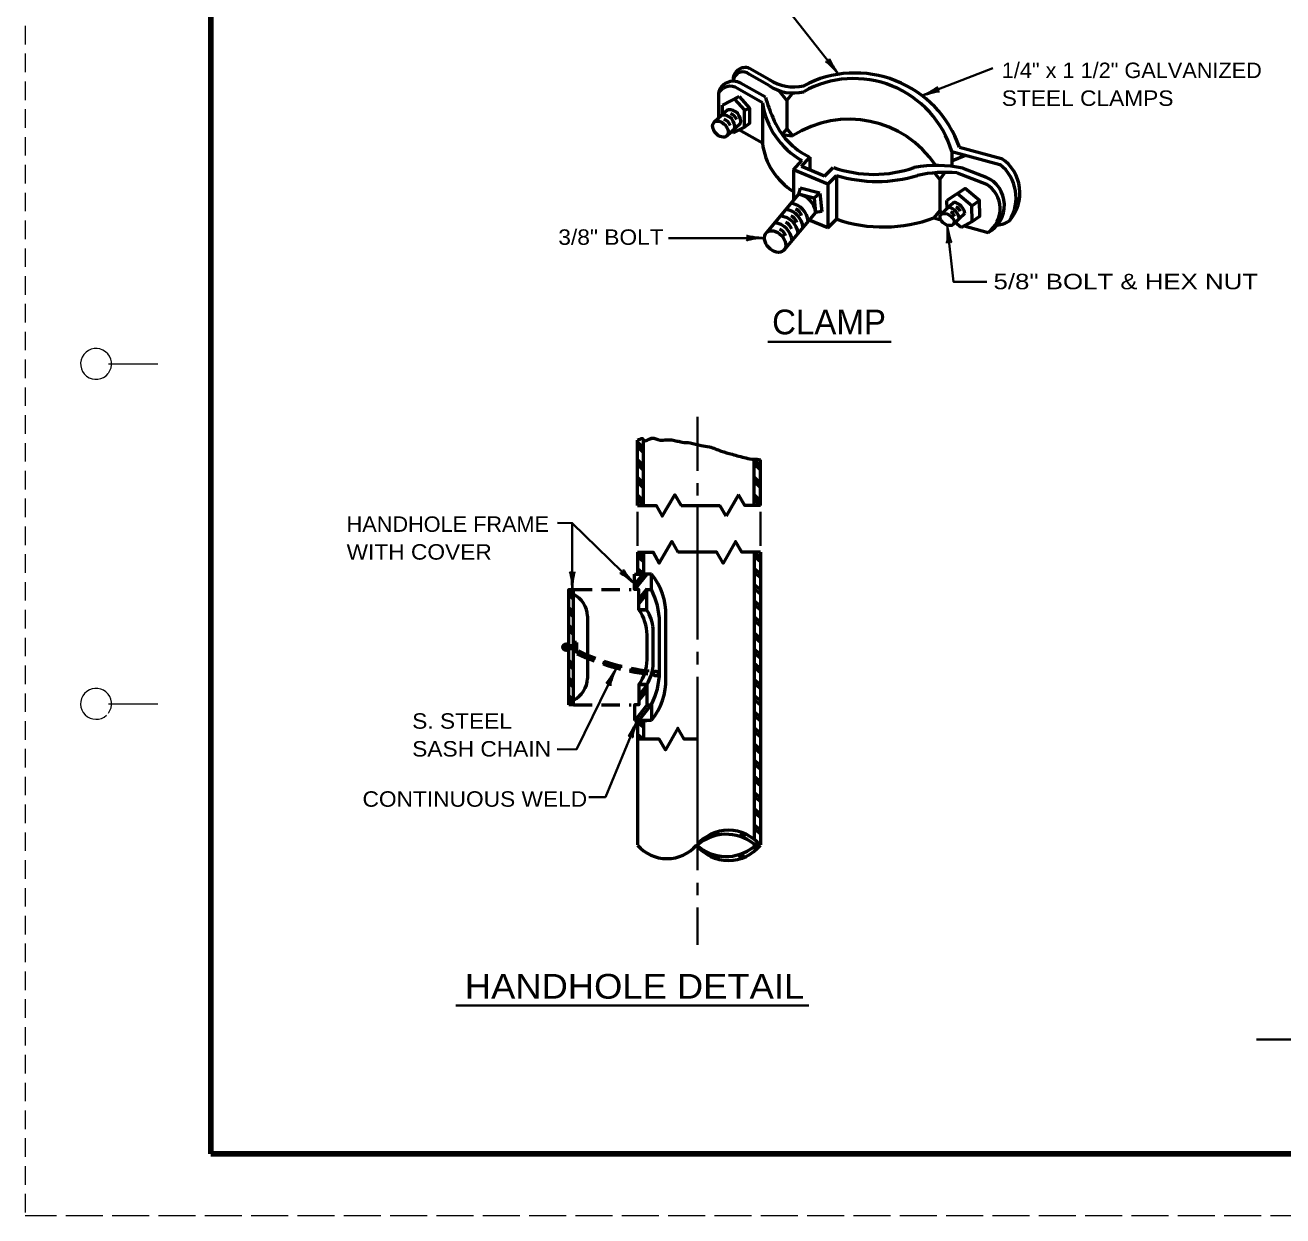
# Model space of a CAD drawing. Extents: x -1 to 679, y -228 to 440.
# Drawn here: x -1 to 202.5, y 0.2 to 192.8 of the extents above; entities that cross this region are included whole.
import ezdxf

# ---------------------------------------------------------------- set-up
doc = ezdxf.new("R2010")
doc.units = 0
doc.linetypes.add('LONG_DASHED', pattern=[7.5, 6, -1.5])
doc.linetypes.add('MEDIUM_DASHED', pattern=[4.5, 3, -1.5])
doc.layers.add('1', color=7, linetype='Continuous', lineweight=35)
doc.layers.add('61', color=7, linetype='Continuous', lineweight=35)

msp = doc.modelspace()

# ---------------------------------------------------------------- hatches: boundary and pattern name
at = {"layer": '1'}
msp.add_hatch(color=256, dxfattribs=at).paths.add_polyline_path([(87.083, 92.208, 1), (85.994, 92.208, 1)])

# ---------------------------------------------------------------- linework, layer by layer
at = {"layer": '1', "linetype": 'MEDIUM_DASHED', "lineweight": 13}
msp.add_line((-0.979, 440.237), (-1.039, 0.197), dxfattribs=at)
at = {"layer": '1', "lineweight": 40}
for p, q in [((120.107, 198.311), (130.625, 184.906)), ((144.15, 181.442), (155.602, 185.881)), ((118.629, 158.401), (103.107, 158.401)), ((119.153, 141.59), (139.165, 141.59)), ((68.685, 34.21), (125.825, 34.21)), ((198.293, 28.717), (261.764, 28.717))]:
    msp.add_line(p, q, dxfattribs=at)
at = {"layer": '1', "lineweight": 53}
for p, q in [((119.441, 184.018), (116.221, 185.858)), ((118.801, 181.178), (114.781, 183.458)), ((119.441, 183.058), (116.221, 184.878)), ((111.181, 181.778), (111.181, 177.758)), ((114.521, 181.298), (111.841, 179.878)), ((118.301, 180.298), (114.281, 182.598)), ((122.241, 180.638), (120.961, 182.278)), ((122.241, 180.638), (123.201, 181.878)), ((112.741, 179.178), (110.481, 177.138)), ((111.841, 178.378), (111.841, 179.878)), ((113.761, 180.898), (115.381, 179.098)), ((118.301, 180.298), (118.301, 173.738)), ((114.761, 176.918), (112.521, 174.898)), ((113.361, 175.678), (113.561, 175.438)), ((118.301, 173.738), (114.501, 175.898)), ((121.761, 175.098), (123.181, 174.918)), ((122.241, 176.098), (123.181, 174.918)), ((150.181, 173.118), (157.001, 171.298)), ((124.641, 169.998), (126.001, 171.498)), ((126.001, 171.498), (126.001, 169.418)), ((148.961, 172.418), (156.741, 170.318)), ((148.961, 172.418), (148.961, 169.998)), ((149.081, 170.958), (151.161, 171.818)), ((123.321, 169.458), (124.681, 170.958)), ((128.901, 167.098), (123.321, 169.458)), ((123.321, 169.458), (123.321, 164.478)), ((128.361, 168.418), (124.641, 169.998)), ((128.361, 168.418), (129.781, 169.838)), ((147.001, 167.898), (147.881, 169.038)), ((150.721, 169.718), (154.501, 168.278)), ((128.901, 167.098), (130.321, 168.518)), ((128.901, 167.098), (128.901, 160.038)), ((130.321, 168.518), (130.321, 161.458)), ((147.001, 167.898), (146.161, 168.958)), ((147.001, 167.898), (147.001, 162.858)), ((149.841, 168.938), (154.561, 167.138)), ((124.161, 165.478), (118.981, 159.298)), ((124.401, 166.458), (124.161, 165.478)), ((126.661, 164.858), (124.161, 165.478)), ((127.581, 165.678), (124.401, 166.458)), ((127.581, 165.678), (126.661, 164.858)), ((127.581, 165.678), (127.921, 162.678)), ((152.181, 163.598), (149.861, 165.538)), ((126.661, 164.858), (126.921, 162.558)), ((149.361, 164.218), (147.141, 162.158)), ((148.181, 163.118), (148.141, 164.478)), ((126.921, 162.558), (121.721, 156.378)), ((128.901, 160.038), (125.881, 161.318)), ((127.921, 162.678), (126.921, 162.558)), ((128.901, 160.038), (130.321, 161.458)), ((147.001, 162.858), (146.061, 161.658)), ((146.061, 161.658), (147.161, 161.358)), ((147.001, 162.858), (147.381, 162.358)), ((151.081, 162.378), (149.241, 160.658)), ((150.481, 160.118), (149.521, 160.918)), ((150.941, 160.358), (154.821, 159.318)), ((98.073, 115.123), (98.073, 125.722)), ((99.073, 124.402), (98.073, 125.402)), ((99.073, 123.682), (98.073, 124.682)), ((99.073, 115.123), (99.073, 125.722)), ((99.073, 121.542), (98.073, 122.542)), ((116.973, 115.123), (116.973, 122.542)), ((117.973, 121.542), (116.973, 122.542)), ((117.973, 115.123), (117.973, 122.542)), ((99.073, 120.822), (98.073, 121.843)), ((117.973, 120.822), (116.973, 121.843)), ((99.073, 118.703), (98.073, 119.703)), ((99.073, 117.983), (98.073, 118.983)), ((117.973, 118.703), (116.973, 119.703)), ((117.973, 117.983), (116.973, 118.983)), ((99.073, 115.843), (98.073, 116.843)), ((99.073, 115.123), (98.073, 116.142)), ((114.453, 116.882), (112.433, 113.382)), ((117.973, 115.843), (116.973, 116.843)), ((117.973, 115.123), (116.973, 116.142)), ((105.133, 115.123), (111.433, 115.123)), ((112.433, 113.382), (111.433, 115.123)), ((98.073, 107.562), (98.073, 104.042)), ((98.073, 107.562), (99.073, 106.742)), ((98.073, 106.922), (99.073, 106.082)), ((99.073, 107.562), (99.073, 104.042)), ((116.973, 107.562), (117.973, 106.742)), ((116.973, 106.922), (117.973, 106.082)), ((117.973, 107.562), (117.973, 60.203)), ((97.573, 104.042), (99.573, 104.042)), ((99.573, 104.042), (97.573, 101.522)), ((98.933, 104.042), (97.573, 102.322)), ((98.073, 104.962), (99.073, 104.123)), ((98.073, 104.302), (98.393, 104.042)), ((100.333, 104.042), (98.313, 104.042)), ((116.973, 104.962), (117.973, 104.123)), ((116.973, 104.302), (117.973, 103.483)), ((116.973, 102.343), (117.973, 101.522)), ((87.733, 100.682), (86.973, 101.442)), ((87.733, 99.983), (86.973, 100.742)), ((87.733, 82.882), (87.733, 101.522)), ((99.573, 101.623), (98.313, 100.042)), ((99.573, 100.822), (98.313, 99.242)), ((116.973, 101.682), (117.973, 100.862)), ((87.733, 97.843), (86.973, 98.602)), ((87.733, 97.123), (86.973, 97.882)), ((99.573, 98.242), (98.313, 98.242)), ((116.973, 99.722), (117.973, 98.903)), ((116.973, 99.082), (117.973, 98.242)), ((87.733, 94.983), (86.973, 95.742)), ((90.013, 97.242), (90.013, 87.162)), ((101.653, 88.162), (101.653, 96.222)), ((102.653, 87.162), (102.653, 97.242)), ((116.973, 97.123), (117.973, 96.282)), ((116.973, 96.462), (117.973, 95.642)), ((87.733, 94.282), (86.973, 95.042)), ((99.633, 90.182), (99.633, 94.222)), ((100.633, 89.182), (100.633, 95.222)), ((116.973, 94.502), (117.973, 93.682)), ((116.973, 93.862), (117.973, 93.022)), ((87.733, 92.442), (86.973, 92.442)), ((87.733, 92.322), (86.973, 92.322)), ((87.733, 92.242), (86.973, 92.242)), ((87.733, 92.242), (86.973, 92.242)), ((87.733, 92.123), (86.973, 92.123)), ((87.733, 92.002), (86.973, 92.002)), ((87.733, 91.942), (86.973, 91.942)), ((88.233, 92.962), (87.733, 92.962)), ((87.853, 92.962), (87.853, 91.442)), ((87.933, 92.962), (87.933, 91.442)), ((87.933, 92.962), (87.933, 91.442)), ((88.013, 92.962), (88.013, 91.442)), ((88.013, 92.962), (88.013, 91.442)), ((88.073, 92.962), (88.073, 91.442)), ((88.133, 92.962), (88.133, 91.442)), ((88.153, 92.962), (88.153, 91.442)), ((88.193, 92.962), (88.193, 91.442)), ((88.233, 92.962), (88.233, 91.442)), ((116.973, 91.903), (117.973, 91.062)), ((87.733, 89.282), (86.973, 90.043)), ((88.233, 91.442), (87.733, 91.442)), ((116.973, 91.242), (117.973, 90.403)), ((116.973, 89.602), (117.973, 88.782)), ((87.733, 88.582), (86.973, 89.322)), ((116.973, 88.962), (117.973, 88.123)), ((87.733, 86.442), (86.973, 87.203)), ((87.733, 85.722), (86.973, 86.483)), ((99.573, 86.022), (98.313, 84.442)), ((116.973, 87.002), (117.973, 86.162)), ((116.973, 86.343), (117.973, 85.522)), ((87.733, 83.582), (86.973, 84.343)), ((87.733, 82.882), (86.973, 83.623)), ((99.573, 85.203), (98.313, 83.642)), ((116.973, 84.382), (117.973, 83.562)), ((116.973, 83.722), (117.973, 82.903)), ((87.733, 82.882), (86.973, 82.882)), ((99.653, 82.882), (97.633, 80.362)), ((100.333, 82.922), (98.273, 80.362)), ((116.973, 81.763), (117.973, 80.942)), ((97.573, 80.362), (99.573, 80.362)), ((98.073, 80.362), (98.073, 77.322)), ((98.073, 80.102), (99.073, 79.263)), ((100.333, 80.362), (98.313, 80.362)), ((98.553, 80.362), (99.073, 79.922)), ((99.073, 80.362), (99.073, 77.322)), ((116.973, 81.123), (117.973, 80.282)), ((98.073, 78.142), (99.053, 77.322)), ((98.073, 77.483), (98.253, 77.322)), ((116.973, 79.162), (117.973, 78.322)), ((116.973, 78.502), (117.973, 77.682)), ((116.973, 76.543), (117.973, 75.722)), ((116.973, 75.903), (117.973, 75.062)), ((116.973, 73.942), (117.973, 73.102)), ((116.973, 73.282), (117.973, 72.442)), ((116.973, 71.322), (117.973, 70.483)), ((116.973, 70.662), (117.973, 69.843)), ((116.973, 68.703), (117.973, 67.882)), ((116.973, 68.062), (117.973, 67.222)), ((116.973, 66.102), (117.973, 65.263)), ((116.973, 65.442), (117.973, 64.623)), ((116.973, 63.482), (117.973, 62.663)), ((110.433, 62.142), (110.633, 61.703)), ((110.913, 62.302), (111.133, 61.802)), ((115.013, 62.203), (114.713, 61.562)), ((115.473, 62.023), (115.193, 61.383)), ((116.973, 62.822), (117.973, 62.002)), ((116.673, 59.722), (117.853, 60.042)), ((116.973, 60.322), (117.613, 60.502)), ((110.613, 58.062), (110.833, 58.523)), ((111.093, 57.922), (111.333, 58.442)), ((114.833, 58.002), (114.533, 58.663)), ((115.313, 58.182), (115.013, 58.822))]:
    msp.add_line(p, q, dxfattribs=at)
at = {"layer": '1'}
for p, q in [((107.773, 120.763), (107.773, 129.502)), ((107.773, 118.763), (107.773, 116.742)), ((98.073, 108.582), (98.073, 114.123)), ((107.773, 115.123), (107.773, 111.362)), ((107.773, 114.722), (107.773, 93.462)), ((117.973, 108.582), (117.973, 114.123)), ((87.519, 112.294), (85.131, 112.307)), ((107.773, 91.442), (107.773, 89.422)), ((107.773, 87.403), (107.773, 56.122)), ((107.773, 54.102), (107.773, 52.082)), ((107.773, 50.082), (107.773, 44.042))]:
    msp.add_line(p, q, dxfattribs=at)
at = {"layer": '1', "linetype": 'MEDIUM_DASHED', "lineweight": 53}
for p, q in [((87.733, 101.522), (97.053, 101.522)), ((87.733, 82.882), (97.053, 82.882))]:
    msp.add_line(p, q, dxfattribs=at)
at = {"layer": '1', "lineweight": 53}
for points in [[(114.521, 181.298), (116.201, 179.438), (116.201, 176.918), (115.381, 176.338), (113.561, 175.438)], [(115.381, 176.338), (115.381, 179.098), (116.201, 179.438)], [(122.241, 180.638), (122.241, 176.098), (121.601, 175.298)], [(150.481, 160.118), (152.261, 161.078), (153.501, 161.938), (153.421, 164.458), (151.101, 166.398), (148.141, 164.478)], [(152.261, 161.078), (152.181, 163.598), (153.421, 164.458)], [(98.073, 115.123), (101.093, 115.123), (102.093, 113.382), (104.113, 116.882), (105.133, 115.123)], [(117.973, 115.123), (115.453, 115.123), (114.453, 116.882)], [(98.073, 107.562), (100.593, 107.562), (101.593, 105.822), (103.613, 109.322), (104.613, 107.562)], [(117.973, 107.562), (114.953, 107.562), (113.953, 109.322), (111.933, 105.822), (110.913, 107.562), (104.613, 107.562)], [(116.973, 107.562), (116.973, 87.123), (116.973, 61.102)], [(98.313, 98.242), (98.313, 101.522), (97.573, 101.522), (97.573, 104.042)], [(98.313, 98.242), (99.573, 98.242), (99.573, 101.522), (100.333, 101.522), (100.333, 104.042)], [(86.973, 82.882), (86.973, 101.522), (87.733, 101.522)], [(99.573, 86.142), (98.313, 86.142), (98.313, 82.882), (97.573, 82.882), (97.573, 80.362)], [(98.313, 86.142), (99.573, 86.142), (99.573, 82.882), (100.333, 82.882), (100.333, 80.362)], [(107.653, 77.322), (105.633, 77.322), (104.613, 79.082), (102.613, 75.582), (101.593, 77.322), (98.073, 77.322), (98.073, 60.203)]]:
    msp.add_lwpolyline(points, dxfattribs=at)
at = {"layer": '1', "lineweight": 40}
msp.add_lwpolyline([(148.224, 160.489), (149.21, 151.327), (154.65, 151.327)], dxfattribs=at)
at = {"layer": '1'}
for points in [[(97.573, 102.459), (87.519, 112.294), (87.519, 101.522)], [(94.602, 88.752), (88.2, 75.673), (85.088, 75.679)], [(98.034, 80.345), (92.887, 67.957), (90.194, 67.957)]]:
    msp.add_lwpolyline(points, dxfattribs=at)
at = {"layer": '1', "lineweight": 53}
for centre, radius in [((86.538, 92.208), 0.545), ((101.059, 87.924), 0.378)]:
    msp.add_circle(centre, radius, dxfattribs=at)
for centre, radius, start, end in [((115.524, 184.021), 1.967, 68.98454, 184.96528), ((115.167, 183.674), 1.613, 48.79801, 173.73367), ((113.595, 181.305), 2.464, 61.16852, 169.07366), ((123.336, 189.995), 7.131, 236.83956, 283.32479), ((133.299, 167.215), 17.892, 19.29143, 117.70819), ((133.089, 167.641), 16.566, 16.7434, 119.30902), ((113.089, 180.813), 2.14, 56.06469, 153.37669), ((123.284, 188.727), 6.854, 235.84201, 284.32234), ((112.883, 177.267), 1.909, 349.61263, 94.38617), ((130.95, 182.087), 12.777, 188.06983, 240.59731), ((139.874, 186.899), 21.84, 195.21089, 204.37149), ((111.911, 176.397), 1.909, 349.61263, 94.38617), ((111.455, 176.011), 1.742, 20.88408, 69.09679), ((112.506, 176.938), 1.742, 20.88408, 69.09679), ((131.129, 182.346), 12.008, 201.80286, 244.70416), ((132.334, 160.727), 16.89, 33.86522, 122.8499), ((129.015, 175.115), 10.803, 187.30417, 238.23787), ((153.241, 165.692), 6.752, 318.38164, 56.15447), ((136.339, 188.098), 19.396, 250.25742, 289.74258), ((146.475, 148.391), 21.748, 78.72641, 99.48511), ((147.907, 149.265), 19.77, 84.35687, 103.10294), ((152.415, 164.901), 6.939, 327.83586, 51.43283), ((136.873, 190.32), 22.763, 253.27137, 286.72862), ((152.516, 163.715), 4.969, 297.71146, 66.56345), ((152.083, 163.134), 4.701, 305.70046, 58.26699), ((123.731, 162.304), 3.193, 4.65558, 82.27962), ((121.684, 159.86), 3.193, 4.74535, 82.35434), ((122.509, 160.869), 3.193, 4.32722, 81.54855), ((123.164, 161.617), 1.531, 14.18506, 70.66849), ((147.854, 161.069), 2.406, 11.41742, 74.57891), ((148.72, 161.894), 2.406, 11.41742, 74.57891), ((148.974, 162.181), 1.432, 21.50211, 64.13038), ((119.913, 157.722), 3.193, 5.19441, 82.73082), ((120.921, 158.791), 3.193, 7.29827, 83.92311), ((121.515, 159.509), 1.531, 14.18506, 70.66849), ((122.37, 160.548), 1.531, 14.18506, 70.66849), ((137.914, 183.47), 23.278, 250.96338, 290.4942), ((148.099, 161.38), 1.432, 21.50211, 64.13038), ((156.114, 164.254), 3.743, 273.11257, 305.52158), ((120.537, 158.409), 1.531, 14.18506, 70.66849), ((92.937, 97.724), 9.729, 357.13004, 40.48815), ((85.9, 97.092), 4.106, 2.02606, 63.44439), ((89.84, 96.116), 11.806, 0.54939, 27.24732), ((92.647, 94.174), 6.982, 0.31998, 35.66459), ((93.502, 94.423), 7.18, 6.38376, 32.16514), ((92.647, 90.22), 6.982, 324.33541, 359.68002), ((93.502, 89.972), 7.18, 327.83486, 353.61624), ((89.84, 88.314), 11.806, 332.75268, 359.45061), ((85.9, 87.302), 4.106, 296.55561, 357.97394), ((92.937, 86.705), 9.729, 319.51185, 2.86996), ((112.451, 54.751), 7.178, 51.54154, 132.04732), ((112.81, 56.013), 6.576, 38.8447, 141.1553), ((102.856, 64.313), 6.317, 220.71167, 319.28832), ((112.81, 64.262), 6.576, 218.22248, 321.77751), ((112.451, 65.523), 7.178, 227.95268, 308.4983), ((116.738, 60.139), 0.294, 307.8273, 52.77092)]:
    msp.add_arc(centre, radius, start, end, dxfattribs=at)
at = {"layer": '1', "linetype": 'MEDIUM_DASHED', "lineweight": 53}
for centre, radius, start, end in [((104.93, 127.366), 39.613, 245.08086, 263.60629), ((104.414, 125.821), 38.237, 245.04728, 263.19799), ((104.079, 124.62), 36.501, 244.77769, 263.49597)]:
    msp.add_arc(centre, radius, start, end, dxfattribs=at)
at = {"layer": '1', "lineweight": 40}
for centre, major_axis, ratio, start_param, end_param in [((130.1, 185.919), (-0.946, 1.49), 0.07063, 6.2823074, 8.5597026), ((129.734, 185.594), (1.225, -1.308), 0.122415, 0.8963533, 3.1415927), ((145.067, 182.094), (-1.609, -0.791), 0.122415, 0.8963533, 3.1415927), ((145.067, 182.094), (-1.609, -0.791), 0.122415, 0.8963533, 3.1415927), ((145.271, 181.65), (-1.701, -0.471), 0.07063, 3.1407148, 5.41811), ((145.271, 181.65), (-1.701, -0.471), 0.07063, 3.1407148, 5.41811), ((148.133, 159.352), (-0.013, 1.765), 0.07063, 3.1407148, 5.41811), ((148.133, 159.352), (-0.013, 1.765), 0.07063, 3.1407148, 5.41811), ((148.615, 159.433), (-0.346, 1.759), 0.122415, 0.8963533, 3.1415927), ((148.615, 159.433), (-0.346, 1.759), 0.122415, 0.8963533, 3.1415927), ((117.538, 158.125), (1.786, 0.156), 0.122415, 0.8963533, 3.1415927), ((117.538, 158.125), (1.786, 0.156), 0.122415, 0.8963533, 3.1415927), ((117.508, 158.612), (1.756, -0.176), 0.07063, 3.1407148, 5.41811), ((117.508, 158.612), (1.756, -0.176), 0.07063, 3.1407148, 5.41811), ((87.243, 102.614), (0.156, -1.786), 0.122415, 0.8963533, 3.1415927), ((87.731, 102.643), (0.176, 1.756), 0.07063, 6.2823074, 8.5597026), ((96.6, 103.024), (1.386, -1.137), 0.122415, 0.8963533, 3.1415927), ((96.6, 103.024), (1.386, -1.137), 0.122415, 0.8963533, 3.1415927), ((96.92, 103.394), (-1.133, 1.354), 0.07063, 6.2823074, 8.5597026), ((96.92, 103.394), (-1.133, 1.354), 0.07063, 6.2823074, 8.5597026), ((93.92, 87.839), (0.93, 1.5), 0.07063, 3.1407148, 5.41811), ((94.371, 87.65), (0.645, 1.672), 0.122415, 0.8963533, 3.1415927), ((97.408, 79.391), (0.836, 1.555), 0.07063, 3.1407148, 5.41811), ((97.87, 79.231), (0.541, 1.709), 0.122415, 0.8963533, 3.1415927)]:
    msp.add_ellipse(centre, major_axis=major_axis, ratio=ratio, start_param=start_param, end_param=end_param, dxfattribs=at)
at = {"layer": '1', "lineweight": 53}
for centre, major_axis, ratio in [((111.501, 176.024), (1.012, -1.124), 0.663346), ((148.192, 161.402), (1.044, -0.75), 0.624582), ((120.353, 157.839), (1.377, -1.452), 0.71432)]:
    msp.add_ellipse(centre, major_axis=major_axis, ratio=ratio, dxfattribs=at)
for points in [[(98.073, 125.722), (98.493, 125.862), (98.933, 125.922), (99.073, 125.722), (100.353, 126.002), (101.733, 125.722), (102.733, 125.763), (104.493, 125.562), (105.293, 125.382), (106.613, 125.263), (108.373, 124.822), (109.713, 124.602), (111.613, 123.942), (113.393, 123.422), (115.613, 122.822), (116.973, 122.542)], [(116.593, 122.623), (117.453, 122.602), (117.973, 122.542)]]:
    msp.add_spline(points, degree=3, dxfattribs=at)
at = {"layer": '61', "lineweight": 13}
for p, q in [((12.441, 138.057), (20.441, 138.057)), ((12.461, 83.037), (20.441, 83.037))]:
    msp.add_line(p, q, dxfattribs=at)
at = {"layer": '61', "lineweight": 158}
msp.add_line((668.081, 10.197), (29.021, 10.217), dxfattribs=at)
at = {"layer": '61', "linetype": 'LONG_DASHED', "lineweight": 13}
msp.add_line((679.021, 0.217), (-1.039, 0.197), dxfattribs=at)
at = {"layer": '61', "lineweight": 158}
msp.add_lwpolyline([(668.061, 430.237), (29.021, 430.237), (29.021, 10.217)], dxfattribs=at)
at = {"layer": '61', "lineweight": 13}
for centre, start, end in [((10.439, 138.038), 322.67175, 321.71615), ((10.439, 83.038), 323.13009, 312.31439)]:
    msp.add_arc(centre, 2.5, start, end, dxfattribs=at)

# ---------------------------------------------------------------- texts
at = {"layer": '1'}
for s, height, width, p in [('1/4" x 1 1/2" GALVANIZED', 2.5, 1.05, (157.045, 184.288)), ('STEEL CLAMPS', 2.5, 1.1, (157.045, 179.788)), ('3/8" BOLT', 2.5, 1.1, (85.266, 157.307)), ('5/8" BOLT & HEX NUT', 2.5, 1.25, (155.71, 150.116)), ('HANDHOLE FRAME', 2.5, 1.05, (50.995, 110.868)), ('WITH COVER', 2.5, 1.1, (50.995, 106.368)), ('S. STEEL', 2.5, 1.1, (61.609, 79.011)), ('SASH CHAIN', 2.5, 1.1, (61.609, 74.511)), ('CONTINUOUS WELD', 2.5, 1.1, (53.568, 66.388)), ('HANDHOLE DETAIL', 4, 1.1, (70.132, 35.336))]:
    msp.add_text(s, height=height, dxfattribs=dict(at, width=width)).set_placement(p)
msp.add_text('CLAMP', height=4, dxfattribs=at).set_placement((119.872, 142.823))

doc.saveas('drawing.dxf')
